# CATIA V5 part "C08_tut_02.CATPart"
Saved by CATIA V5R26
Part number: Part1
Bounding box of the stored display mesh (mm): x -50.5 to 35, y -44.738 to 44.738, z 0 to 30
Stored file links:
  D:\_Deepak\CATIA\CATIA V5 2015 Parts Files\Tutorial Files\Tutorials\c08_catia_v5_6r2015_tut\C08_tut_02.CATPart
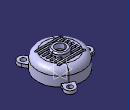
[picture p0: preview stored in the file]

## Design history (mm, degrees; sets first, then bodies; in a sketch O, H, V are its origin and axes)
Body1 (main body)
  Sketch1 on yz-plane, origin (0, 0, 0), H (0, 1, 0), V (0, 0, 1)
    line L1 (0, 0) -> (0, 25)
    line L2 (0, 25) -> (25, 25)
    point P2 (35, 25)
    line L3 (35, 15) -> (35, 0)
    point P3 (35, 0)
    line L4 (35, 0) -> (0, 0)
    reference intersected line E1 through (0, 0) direction (0, 1) from zx-plane
    axis line L5 (0, 41.2428) -> (0, -12.5007)
    point P4 (0, 41.2428)
    arc A1 centre (25, 15) radius 10 from (25, 25) to (35, 15) cw
    radius about axis P3 L5 = 35
    distance P2 P3 = 25
    radius A1 = 10
    horizontal: L2 H, L4 H
    coincidence: P3 H, L1 E1, P4 L1, L2 P2, L3 P2
    vertical: L3 V, L5 V
    tangency: A1 L2, A1 L3
  Shaft1: profile Sketch1, axis Sketch1.L5, angle 360
  Shell1: ExtOffset 0, Face face of Shaft1 from Sketch1.L4, IntOffset 3
  Sketch2 on face of Shaft1 from Sketch1.L4, origin (0, 0, 0), H (1, 0, 0), V (0, -1, 0)
    projected circle E1 centre (0, 0) radius 35 from edge [face of Shaft1 from Sketch1.L3 | face of Shaft1 from Sketch1.L4]
    projected arc E2 centre (0, 0) radius 35 from (-34.0735, 8) to (-34.0735, -8) ccw from edge [face of Shaft1 from Sketch1.L3 | face of Shaft1 from Sketch1.L4]
    point P1 (-34.0735, 8)
    line L1 (-34.0735, 8) -> (-42.5, 8)
    arc A1 centre (-42.5, 0) radius 8 from (-42.5, 8) to (-42.5, -8) ccw
    point P3 (-42.5, 0)
    line L2 (-42.5, -8) -> (-34.0735, -8)
    point P5 (-34.0735, -8)
    circle A2 centre (-42.5, 0) radius 4
    radius A1 = 8
    radius A2 = 4
    distance P3 V = 42.5
    coincidence: P1 E1, P3 H, P5 E1
    horizontal: L1 H, L2 H
    tangency: A1 L1, L2 A1
  Pad1: profile Sketch2, direction (0, 0, 1), length 5
  CircPattern1: of Pad1, instances 3, angular step 120 {= 360.0*1 deg/CircPattern1.AngularNumber}, axis from face of Shaft1 from Sketch1.L3
  Sketch3 on face of Shaft1 from Sketch1.L2, origin (0, 0, 25), H (1, 0, 0), V (0, 1, 0)
    point P1 (0, -18)
    line L1 (20, -19.75) -> (-20, -19.75)
    line L2 (-20, -16.25) -> (20, -16.25)
    point P5 (-20, -16.25)
    point P6 (20, -18)
    point P7 (-20, -18)
    arc A1 centre (20, -18) radius 1.75 from (20, -19.75) to (20, -16.25) ccw
    arc A2 centre (-20, -18) radius 1.75 from (-20, -16.25) to (-20, -19.75) ccw
    point P8 (-20, -16.25)
    axis line L3 (20, -18) -> (-20, -18)
    distance P7 P6 = 40
    distance H P6 = 18
    distance L2 L1 = 3.5
    coincidence: P1 V, A2 P5, P5 P8
    horizontal: L1 H, L2 H, L3 H
    equidistance: L1 L2 P1
    tangency: A1 L1, A2 L1, L2 A2, L2 A1
    symmetry: P7 P6 V
  Pocket1: profile Sketch3, direction (0, 0, -1), length 8
  RectPattern1: of Pocket1, direction 1 instances 7, spacing 6, along yz-plane
  Sketch4 on face of Shell1, origin (0, 0, 22), H (1, 0, 0), V (0, -1, 0)
    circle A1 centre (0, 0) radius 7.5
    circle A2 centre (0, 0) radius 12.5
    radius A2 = 12.5
    radius A1 = 7.5
  Pad2: profile Sketch4, direction (0, 0, 1), length 8
  Sketch5 on face of Pad2, origin (0, 0, 22), H (1, 0, 0), V (0, -1, 0)
    circle A1 centre (0, 0) radius 7.5
    reference projected arc E1 centre (0, 0) radius 7.5 from (7.293, -1.75) to (7.293, 1.75) ccw from edge [face of Pad2 | face of Pad2 from Sketch4.A1]
    coincidence: E1 A1
  Pocket2: profile Sketch5, direction (0, 0, 1), length 8
  Fillet1: radius 2, on edge [end face of Pad2 | face of Pad2 from Sketch4.A2]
